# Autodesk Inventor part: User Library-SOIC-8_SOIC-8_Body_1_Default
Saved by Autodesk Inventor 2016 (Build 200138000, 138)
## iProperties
Created: 2012-01
Part Number: User Library-SOIC-8_SOIC-8_Body_1_Default
Document SubType Name: Modeling
Designer: Trevor
Density: 1 g/cm^3
Material: Generic
Appearance: Default
Author: Trevor
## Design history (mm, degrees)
feature "Base1"
node "Imported1"
